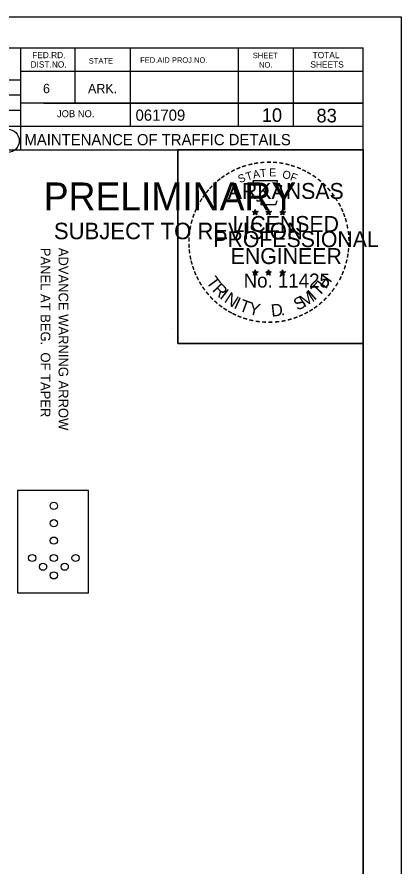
# Model space of a CAD drawing. Extents: x 1397271 to 1411271, y 376395 to 377888.
# Drawn here: x 1406267 to 1406605, y 377141 to 377888 of the extents above; entities that cross this region are included whole.
import ezdxf

# ---------------------------------------------------------------- set-up
doc = ezdxf.new("R2010")
doc.units = 0
for name, color, linetype in [('Default', 7, 'Continuous'), ('R_Border', 7, 'Continuous'), ('R_Border PE', 7, 'Continuous'), ('R_Border Prem', 7, 'Continuous'), ('R_Draft', 7, 'Continuous'), ('R_MOT', 7, 'Continuous'), ('R_No Plot', 7, 'Continuous')]:
    doc.layers.add(name, color=color, linetype=linetype)

msp = doc.modelspace()

# ---------------------------------------------------------------- linework, layer by layer
at = {"layer": 'R_Border'}
for p, q in [((1404358, 377860.72), (1406571.3, 377860.72)), ((1406269.59, 377860.72), (1406269.59, 377771.12)), ((1406317.47, 377860.72), (1406317.47, 377812.14)), ((1406366.06, 377860.72), (1406366.06, 377791.56)), ((1406461.12, 377860.72), (1406461.12, 377791.56)), ((1406509.7, 377860.72), (1406509.7, 377791.56)), ((1406571.3, 376422.47), (1406571.3, 377860.72)), ((1406571.3, 377840.14), (1406269.59, 377840.14)), ((1406571.3, 377840.28), (1406571.3, 377840.28)), ((1405995.47, 377832.58), (1406269.59, 377832.58)), ((1405995.47, 377819.56), (1406269.59, 377819.56)), ((1405995.47, 377805.98), (1406269.59, 377805.98)), ((1406571.3, 377812.14), (1406269.59, 377812.14)), ((1406290.31, 377812.14), (1406571.3, 377812.14)), ((1406571.3, 377791.56), (1405995.47, 377791.56)), ((1406269.59, 377771.12), (1406571.3, 377771.12))]:
    msp.add_line(p, q, dxfattribs=at)
msp.add_circle((1406258.3, 377779.07), 10.27, dxfattribs=at)
at = {"layer": 'R_Border PE'}
for p, q in [((1406473.88, 377716.84), (1406476.32, 377716.06)), ((1406473.88, 377716.84), (1406475.65, 377716.53)), ((1406473.88, 377716.84), (1406475.54, 377715.99)), ((1406474.81, 377713.98), (1406476.32, 377716.06)), ((1406476.32, 377718.62), (1406476.03, 377716.85)), ((1406476.32, 377716.06), (1406476.32, 377718.62)), ((1406476.32, 377718.62), (1406476.67, 377716.87)), ((1406478.75, 377716.84), (1406476.32, 377716.06)), ((1406477.81, 377713.98), (1406476.32, 377716.06)), ((1406478.75, 377716.84), (1406476.75, 377716.5)), ((1406477.81, 377713.98), (1406476.85, 377716.02)), ((1406478.75, 377716.84), (1406477.32, 377716.13)), ((1406485.57, 377716.84), (1406488.01, 377716.06)), ((1406485.57, 377716.84), (1406487.34, 377716.53)), ((1406485.57, 377716.84), (1406487.23, 377715.99)), ((1406486.5, 377713.98), (1406488.01, 377716.06)), ((1406488.01, 377718.62), (1406487.73, 377716.85)), ((1406488.01, 377716.06), (1406488.01, 377718.62)), ((1406488.01, 377718.62), (1406488.36, 377716.87)), ((1406490.44, 377716.84), (1406488.01, 377716.06)), ((1406489.5, 377713.98), (1406488.01, 377716.06)), ((1406490.44, 377716.84), (1406488.44, 377716.5)), ((1406489.5, 377713.98), (1406488.54, 377716.02)), ((1406490.44, 377716.84), (1406489.01, 377716.13)), ((1406497.92, 377716.76), (1406500.36, 377715.98)), ((1406497.92, 377716.76), (1406499.69, 377716.44)), ((1406497.92, 377716.76), (1406499.58, 377715.9)), ((1406498.85, 377713.9), (1406500.36, 377715.98)), ((1406500.36, 377718.53), (1406500.07, 377716.77)), ((1406500.36, 377715.98), (1406500.36, 377718.53)), ((1406500.36, 377718.53), (1406500.7, 377716.78)), ((1406502.79, 377716.76), (1406500.36, 377715.98)), ((1406501.85, 377713.9), (1406500.36, 377715.98)), ((1406502.79, 377716.76), (1406500.79, 377716.41)), ((1406501.85, 377713.9), (1406500.89, 377715.94)), ((1406502.79, 377716.76), (1406501.36, 377716.04)), ((1406474.81, 377713.98), (1406475.69, 377715.69)), ((1406474.81, 377713.98), (1406476.31, 377715.5)), ((1406477.81, 377713.98), (1406476.31, 377715.48)), ((1406486.5, 377713.98), (1406487.38, 377715.69)), ((1406486.5, 377713.98), (1406488, 377715.5)), ((1406489.5, 377713.98), (1406488, 377715.48)), ((1406498.85, 377713.9), (1406499.73, 377715.61)), ((1406498.85, 377713.9), (1406500.35, 377715.42)), ((1406501.85, 377713.9), (1406500.35, 377715.4)), ((1406473.85, 377663.83), (1406476.29, 377663.05)), ((1406473.85, 377663.83), (1406475.62, 377663.51)), ((1406473.85, 377663.83), (1406475.51, 377662.97)), ((1406476.29, 377665.61), (1406476.01, 377663.84)), ((1406476.29, 377663.05), (1406476.29, 377665.61)), ((1406476.29, 377665.61), (1406476.64, 377663.86)), ((1406478.72, 377663.83), (1406476.29, 377663.05)), ((1406478.72, 377663.83), (1406476.72, 377663.49)), ((1406478.72, 377663.83), (1406477.3, 377663.11)), ((1406485.53, 377663.83), (1406487.98, 377663.05)), ((1406485.53, 377663.83), (1406487.31, 377663.51)), ((1406485.53, 377663.83), (1406487.19, 377662.97)), ((1406487.98, 377665.61), (1406487.69, 377663.84)), ((1406487.98, 377663.05), (1406487.98, 377665.61)), ((1406487.98, 377665.61), (1406488.32, 377663.86)), ((1406490.41, 377663.83), (1406487.98, 377663.05)), ((1406490.41, 377663.83), (1406488.4, 377663.49)), ((1406490.41, 377663.83), (1406488.98, 377663.11)), ((1406497.9, 377663.76), (1406500.35, 377662.98)), ((1406497.9, 377663.76), (1406499.67, 377663.44)), ((1406497.9, 377663.76), (1406499.56, 377662.9)), ((1406500.35, 377665.54), (1406500.06, 377663.77)), ((1406500.35, 377662.98), (1406500.35, 377665.54)), ((1406500.35, 377665.54), (1406500.69, 377663.79)), ((1406502.78, 377663.76), (1406500.35, 377662.98)), ((1406502.78, 377663.76), (1406500.77, 377663.42)), ((1406502.78, 377663.76), (1406501.35, 377663.04)), ((1406474.78, 377660.97), (1406476.29, 377663.05)), ((1406474.78, 377660.97), (1406475.66, 377662.68)), ((1406474.78, 377660.97), (1406476.28, 377662.49)), ((1406477.79, 377660.97), (1406476.28, 377662.47)), ((1406477.79, 377660.97), (1406476.29, 377663.05)), ((1406477.79, 377660.97), (1406476.83, 377663.01)), ((1406486.47, 377660.97), (1406487.98, 377663.05)), ((1406486.47, 377660.97), (1406487.35, 377662.68)), ((1406486.47, 377660.97), (1406487.96, 377662.49)), ((1406489.47, 377660.97), (1406487.96, 377662.47)), ((1406489.47, 377660.97), (1406487.98, 377663.05)), ((1406489.47, 377660.97), (1406488.51, 377663.01)), ((1406498.83, 377660.9), (1406500.35, 377662.98)), ((1406498.83, 377660.9), (1406499.72, 377662.61)), ((1406498.83, 377660.9), (1406500.33, 377662.42)), ((1406501.84, 377660.9), (1406500.33, 377662.4)), ((1406501.84, 377660.9), (1406500.35, 377662.98)), ((1406501.84, 377660.9), (1406500.88, 377662.94))]:
    msp.add_line(p, q, dxfattribs=at)
for points in [[(1406474.17, 377743.99), (1406476.05, 377738.2)], [(1406498.74, 377737.53), (1406499.74, 377739.52), (1406494.94, 377739.35), (1406495.98, 377743.99), (1406474.17, 377743.99)], [(1406477.61, 377727.03), (1406477.61, 377726.42), (1406481.55, 377726.28), (1406481.17, 377722.97), (1406494.26, 377722.97), (1406495.67, 377726.72)], [(1406476.32, 377718.62), (1406477.81, 377713.98), (1406473.88, 377716.84), (1406478.75, 377716.84), (1406474.81, 377713.98), (1406476.32, 377718.62)], [(1406488.01, 377718.62), (1406489.5, 377713.98), (1406485.57, 377716.84), (1406490.44, 377716.84), (1406486.5, 377713.98), (1406488.01, 377718.62)], [(1406500.36, 377718.53), (1406501.85, 377713.9), (1406497.92, 377716.76), (1406502.79, 377716.76), (1406498.85, 377713.9), (1406500.36, 377718.53)], [(1406476.29, 377665.61), (1406477.79, 377660.97), (1406473.85, 377663.83), (1406478.72, 377663.83), (1406474.78, 377660.97), (1406476.29, 377665.61)], [(1406487.98, 377665.61), (1406489.47, 377660.97), (1406485.53, 377663.83), (1406490.41, 377663.83), (1406486.47, 377660.97), (1406487.98, 377665.61)], [(1406500.35, 377665.54), (1406501.84, 377660.9), (1406497.9, 377663.76), (1406502.78, 377663.76), (1406498.83, 377660.9), (1406500.35, 377665.54)]]:
    msp.add_lwpolyline(points, dxfattribs=at)
for centre, radius in [((1406476.31, 377716.06), 1.21), ((1406476.31, 377716.06), 1.01), ((1406476.31, 377716.06), 0.81), ((1406476.31, 377716.06), 0.694), ((1406476.31, 377716.06), 0.523), ((1406476.31, 377716.06), 0.347), ((1406476.31, 377716.06), 0.208), ((1406488.01, 377716.06), 1.21), ((1406488.01, 377716.06), 1.01), ((1406488.01, 377716.06), 0.81), ((1406488.01, 377716.06), 0.694), ((1406488.01, 377716.06), 0.523), ((1406488.01, 377716.06), 0.347), ((1406488.01, 377716.06), 0.208), ((1406500.35, 377715.97), 1.21), ((1406500.35, 377715.97), 1.01), ((1406500.35, 377715.97), 0.81), ((1406500.35, 377715.97), 0.694), ((1406500.35, 377715.97), 0.523), ((1406500.35, 377715.97), 0.347), ((1406500.35, 377715.97), 0.208), ((1406476.29, 377663.05), 1.21), ((1406476.29, 377663.05), 1.01), ((1406476.29, 377663.05), 0.81), ((1406476.29, 377663.05), 0.694), ((1406487.97, 377663.05), 1.21), ((1406487.97, 377663.05), 1.01), ((1406487.97, 377663.05), 0.81), ((1406487.97, 377663.05), 0.694), ((1406500.34, 377662.98), 1.21), ((1406500.34, 377662.98), 1.01), ((1406500.34, 377662.98), 0.81), ((1406500.34, 377662.98), 0.694), ((1406476.29, 377663.05), 0.523), ((1406476.29, 377663.05), 0.347), ((1406476.29, 377663.05), 0.208), ((1406487.97, 377663.05), 0.523), ((1406487.97, 377663.05), 0.347), ((1406487.97, 377663.05), 0.208), ((1406500.34, 377662.98), 0.523), ((1406500.34, 377662.98), 0.347), ((1406500.34, 377662.98), 0.208)]:
    msp.add_circle(centre, radius, dxfattribs=at)
at = {"layer": 'R_MOT'}
msp.add_lwpolyline([(1406267.18, 377471.53), (1406267.18, 377381.5), (1406329.47, 377381.5), (1406329.47, 377471.53)], close=True, dxfattribs=at)
for centre in [(1406299.04, 377458.04), (1406299.04, 377442.75), (1406299.04, 377427.46), (1406279.95, 377412.17), (1406299.04, 377412.17), (1406318.12, 377412.17), (1406289.5, 377404.53), (1406308.58, 377404.53), (1406299.04, 377396.88)]:
    msp.add_circle(centre, 3.17, dxfattribs=at)
at = {"layer": 'R_No Plot'}
for p, q in [((1404271.19, 377887.98), (1406604.57, 377887.98)), ((1406403.52, 377613.86), (1406403.52, 377613.86))]:
    msp.add_line(p, q, dxfattribs=at)
for points in [[(1404271.14, 377887.98), (1406604.57, 377887.98), (1406604.57, 376394.59), (1404271.14, 376394.59)], [(1405995.47, 377860.72), (1405995.47, 377791.56), (1406245.6, 377791.56), (1406245.6, 377771.12), (1406408, 377771.12), (1406408, 377600.79), (1406571.3, 377600.79), (1406571.3, 376422.47), (1404358, 376422.47), (1404358, 377860.72)], [(1406408, 377771.34), (1406571.3, 377771.34), (1406571.3, 377600.79), (1406408, 377600.79)]]:
    msp.add_lwpolyline(points, close=True, dxfattribs=at)

# ---------------------------------------------------------------- texts
at = {"layer": 'Default'}
for s, p in [('PANEL AT BEG.  OF TAPER', (1406287.42, 377684.98)), ('ADVANCE WARNING ARROW', (1406303.18, 377684.98))]:
    msp.add_text(s, height=8.5402, rotation=270, dxfattribs=at).set_placement(p)
at = {"layer": 'R_Border'}
for s, height, p in [('FED.RD.', 5.474, (1406279.95, 377851.76)), ('STATE', 4.788, (1406329.79, 377847)), ('FED.AID PROJ.NO.', 4.7881, (1406375.02, 377847.7)), ('SHEET', 4.788, (1406474.14, 377851.76)), ('TOTAL', 5.474, (1406526.78, 377851.76)), ('DIST.NO.', 5.474, (1406278.55, 377843.5)), ('NO.', 4.788, (1406479.6, 377843.5)), ('SHEETS', 5.474, (1406524.82, 377843.5)), ('6', 8.21, (1406289.47, 377820.96)), ('ARK.', 8.206, (1406329.09, 377820.96)), ('JOB NO.', 6.155, (1406301.79, 377799.82)), ('061709', 9.8, (1406370.93, 377796.74)), ('MAINTENANCE OF TRAFFIC DETAILS', 9.8002, (1406273.11, 377775.2))]:
    msp.add_text(s, height=height, rotation=360, dxfattribs=at).set_placement(p)
at = {"layer": 'R_Border PE'}
for s, height, rotation, p in [('-', 11.2, 5.89682, (1406480.5, 377755.47)), ('-', 11.2, 0.18623, (1406485.9, 377755.97)), ('-', 11.2, 357.74304, (1406490.96, 377755.88)), ('-', 11.2, 28.79182, (1406456.53, 377747.77)), ('-', 11.2, 24.30721, (1406460.96, 377749.99)), ('-', 11.2, 19.17608, (1406465.4, 377751.88)), ('-', 11.2, 13.63015, (1406470.65, 377753.56)), ('A', 7, 11.21318, (1406474.83, 377745.81)), ('-', 11.2, 10.21935, (1406475.4, 377754.7)), ('T', 7, 6.02276, (1406480.77, 377746.97)), ('E', 7, 0.83234, (1406488.51, 377747.74)), ('-', 11.2, 352.16172, (1406496.17, 377755.49)), ('-', 11.2, 347.20489, (1406501.21, 377754.69)), ('-', 11.2, 342.3362, (1406505.65, 377753.61)), ('-', 11.2, 337.85509, (1406510.8, 377752.04)), ('-', 11.2, 334.12109, (1406515.21, 377750.15)), ('-', 11.2, 38.95066, (1406444.97, 377739.77)), ('-', 11.2, 36.23174, (1406448.31, 377742.42)), ('-', 11.2, 34.06357, (1406452.35, 377745.18)), ('S', 7, 21.59401, (1406462.65, 377741.73)), ('T', 7, 16.4036, (1406469.05, 377744.05)), ('O', 7, 350.4515, (1406499.74, 377746.27)), ('F', 7, 340.07066, (1406506.41, 377744.67)), ('-', 11.2, 329.64089, (1406519.27, 377748.17)), ('-', 11.2, 325.86266, (1406523.77, 377745.64)), ('-', 11.2, 320.52971, (1406528.04, 377742.66)), ('-', 11.2, 48.42305, (1406438.81, 377733.51)), ('-', 11.2, 42.96224, (1406441.94, 377736.85)), ('ARKANSAS', 14, 360, (1406452.14, 377727.97)), ('-', 11.2, 315.57859, (1406532.23, 377739.24)), ('-', 11.2, 54.23247, (1406433.09, 377726.14)), ('-', 11.2, 50.61417, (1406435.99, 377730.11)), ('-', 11.2, 309.87973, (1406536.21, 377735.39)), ('-', 11.2, 306.65218, (1406539.89, 377731.18)), ('-', 11.2, 62.87135, (1406428.63, 377718.15)), ('-', 11.2, 58.07063, (1406430.82, 377722.45)), ('-', 9.8, 303.67529, (1406543.29, 377727.2)), ('-', 11.2, 299.66835, (1406545.52, 377722.95)), ('-', 11.2, 67.77427, (1406426.82, 377713.87)), ('DWB', 0.07, 360, (1406476.23, 377716.03)), ('DWB', 0.07, 360, (1406487.92, 377716.03)), ('DWB', 0.07, 360, (1406500.27, 377715.95)), ('-', 11.2, 294.66279, (1406547.79, 377718.67)), ('-', 11.2, 75.46096, (1406423.9, 377704.46)), ('-', 11.2, 72.39447, (1406425.28, 377709.46)), ('LICENSED', 14, 360, (1406456.32, 377698.93)), ('-', 11.2, 290.57283, (1406549.59, 377714.63)), ('-', 11.2, 285.12326, (1406551.23, 377710.57)), ('-', 11.2, 81.20126, (1406422.98, 377699.47)), ('-', 11.2, 280.54934, (1406552.63, 377705.37)), ('-', 11.2, 89.06224, (1406422.27, 377689.73)), ('-', 11.2, 85.18634, (1406422.45, 377694.64)), ('PROFESSIONAL', 14.0002, 360, (1406439.35, 377685.6)), ('-', 11.2, 276.59616, (1406553.76, 377700)), ('-', 11.2, 274.33011, (1406554.18, 377694.94)), ('-', 11.2, 94.19588, (1406422.52, 377684.65)), ('-', 11.2, 269.94067, (1406554.42, 377690.52)), ('-', 11.2, 98.94793, (1406423.02, 377679.99)), ('ENGINEER', 14, 360, (1406454.66, 377670.72)), ('-', 11.2, 260.99529, (1406553.79, 377681.28)), ('-', 11.2, 263.5172, (1406554.29, 377685.86)), ('-', 11.2, 101.71495, (1406423.97, 377674.85)), ('-', 11.2, 105.45785, (1406425.1, 377670.69)), ('-', 11.2, 255.7626, (1406553.02, 377676.53)), ('-', 11.2, 109.08742, (1406426.61, 377666.27)), ('-', 11.2, 114.06432, (1406428.38, 377662.1)), ('-', 11.2, 247.88866, (1406550.19, 377666.78)), ('-', 11.2, 252.86809, (1406551.75, 377671.49)), ('-', 11.2, 115.72885, (1406430.52, 377657.77)), ('T', 10.78, 306.04056, (1406432.61, 377654.92)), ('No. 11425', 12.299, 360, (1406466.06, 377650.07)), ('DWB', 0.07, 360, (1406476.2, 377663.02)), ('DWB', 0.07, 360, (1406487.89, 377663.02)), ('DWB', 0.07, 360, (1406500.26, 377662.95)), ('H', 10.78, 54.60883, (1406538.45, 377648.16)), ('-', 11.2, 244.61971, (1406548.36, 377662.38)), ('-', 11.2, 120.44712, (1406433.02, 377653.67)), ('-', 11.2, 125.89344, (1406435.84, 377649.74)), ('R', 10.78, 314.00497, (1406437.95, 377647.58)), ('I', 10.78, 321.96938, (1406444.25, 377641.06)), ('T', 10.78, 46.64442, (1406532.23, 377641.57)), ('-', 11.2, 233.84524, (1406542.79, 377652.54)), ('-', 11.2, 239.07125, (1406545.6, 377657.12)), ('-', 11.2, 130.71812, (1406439.07, 377645.88)), ('-', 11.2, 134.22381, (1406442.69, 377642.07)), ('N', 10.78, 326.50021, (1406448.22, 377637.76)), ('I', 10.78, 335.36034, (1406456.68, 377632.26)), ('S', 10.78, 26.9312, (1406513.43, 377629.45)), ('M', 10.78, 32.65632, (1406519.31, 377632.29)), ('I', 10.78, 42.11359, (1406528.29, 377638.22)), ('-', 11.2, 225.76533, (1406536.42, 377644.63)), ('-', 11.2, 231.25377, (1406539.78, 377648.58)), ('-', 11.2, 138.93382, (1406446.37, 377638.82)), ('-', 11.2, 144.64634, (1406450.26, 377635.98)), ('T', 10.78, 339.89117, (1406461.31, 377629.96)), ('Y', 10.78, 347.85558, (1406469.83, 377626.85)), ('D', 10.78, 6.39691, (1406490.72, 377624.34)), ('-', 11.2, 215.73633, (1406528.93, 377637.77)), ('-', 11.2, 221.08509, (1406532.77, 377641.07)), ('-', 11.2, 148.08978, (1406454.19, 377633.38)), ('-', 11.2, 151.57039, (1406458.24, 377631.1)), ('-', 11.2, 154.60019, (1406461.89, 377629.37)), ('.', 10.78, 13.76417, (1406499.06, 377625.23)), ('-', 11.2, 204.25161, (1406516.91, 377630.4)), ('-', 11.2, 207.35684, (1406521.28, 377632.64)), ('-', 11.2, 212.24909, (1406525.19, 377635.06)), ('-', 11.2, 158.56121, (1406466.26, 377627.6)), ('-', 11.2, 162.79826, (1406471.07, 377626.11)), ('-', 11.2, 167.55551, (1406476.08, 377624.96)), ('-', 11.2, 173.11546, (1406481.48, 377624.19)), ('-', 11.2, 176.51827, (1406486.72, 377623.82)), ('-', 11.2, 181.59176, (1406491.92, 377623.95)), ('-', 11.2, 185.81666, (1406497.59, 377624.48)), ('-', 11.2, 191.28576, (1406502.74, 377625.41)), ('-', 11.2, 195.47429, (1406507.84, 377626.8)), ('-', 11.2, 200.71842, (1406512.58, 377628.49))]:
    msp.add_text(s, height=height, rotation=rotation, dxfattribs=at).set_placement(p)
at = {"layer": 'R_Border Prem'}
for s, height, p in [('PRELIMINARY', 24.5005, (1406290.16, 377717.92)), ('DWB', 0.07, (1406291.65, 377730.85)), ('SUBJECT TO REVISION', 14.5261, (1406299.08, 377692.52))]:
    msp.add_text(s, height=height, rotation=360, dxfattribs=at).set_placement(p)
at = {"layer": 'R_Draft'}
for s, p in [('10', (1406482.03, 377795.68)), ('83', (1406530.17, 377795.27))]:
    msp.add_text(s, height=12, rotation=360, dxfattribs=at).set_placement(p)

doc.saveas('drawing.dxf')
